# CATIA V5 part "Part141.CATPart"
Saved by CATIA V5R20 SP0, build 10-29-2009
Part number: IA 5717SF
Revision: ANY
Definition: UNKNOWN
Nomenclature: IA 5717SF
Source: Unknown
Bounding box of the stored display mesh (mm): x -2.85 to 2.85, y -7.925 to 9.045, z -2.711 to 2.711
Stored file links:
  C:\Users\Utente\Desktop\IO LAVORO\3D X SITO CF\CUMSA\3D files FA\FA 105700\Part141.CATPart

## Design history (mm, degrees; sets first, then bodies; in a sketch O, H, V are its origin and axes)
Body1 "Cortar-Extruir2" (main body)
  Solid1: solid without history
